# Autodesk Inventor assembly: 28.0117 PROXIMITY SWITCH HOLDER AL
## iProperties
Created: 2007-05
Part Number: 28.0117 PROXIMITY SWITCH HOLDER AL
Document SubType Name: Assembly
Designer: Andy Moles
Author: Andy Moles
